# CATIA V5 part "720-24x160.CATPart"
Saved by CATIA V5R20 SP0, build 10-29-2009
Part number: 720-24x160
Definition: NONE
Nomenclature: 720-24x160
Source: Unknown
Description: 720-24x160
Bounding box of the stored display mesh (mm): x 0 to 160, y -12 to 12, z -12 to 12
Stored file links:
  C:\Users\Utente\Desktop\IO LAVORO\3D X SITO CF\X SITO\720\720-24x160.CATPart

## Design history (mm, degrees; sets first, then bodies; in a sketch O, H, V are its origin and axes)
Body1 "720-24x160" (main body)
  Solid1: solid without history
